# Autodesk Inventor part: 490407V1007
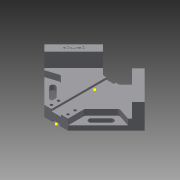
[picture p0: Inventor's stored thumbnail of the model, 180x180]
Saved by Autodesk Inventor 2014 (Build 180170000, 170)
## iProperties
Created: 2019-04
Part Number: 490407V1007
Material: Generic
Document SubType Name: Modeling
Designer: kh
Density: 1 g/cm^3
Appearance: Default
Author: kh
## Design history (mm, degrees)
sketch "Sketch1"
  geometry: L1 (-84.853, 0)-(-35.355, 49.497); L2 (-35.355, 49.497)-(-14.005, 28.147); L3 (-14.005, 28.147)-(14.005, 28.147); L4 (14.005, 28.147)-(35.355, 49.497); L5 (35.355, 49.497)-(84.853, 0); L6 (84.853, 0)-(20, -64.853); L7 (20, -64.853)-(-20, -64.853); L8 (-20, -64.853)-(-84.853, 0); L9 (0, 130.154)-(0, -117.428); L10 (-35.355, 49.497)-(0, 84.853); L11 (35.355, 49.497)-(29.217, 55.636); L12 (29.217, 55.636)-(0, 84.853); L13 (-74.246, -10.607)-(-24.749, 38.891); L14 (24.749, 38.891)-(74.246, -10.607); 1 further point
  constraints: 28 end point, 7 perpendicular, 7 point on line, 4 parallel, 1 vertical
  dimensions: "d6" = 120 distance between parallel lines of L6 L1; "d7" = 120 distance between parallel lines of L8 L5; "d8" = 60 distance from line of point (0, 0) L5; "d9" = 60 distance from line of point (0, 0) L1; "d10" = 40 distance of L6.end L7.end; "d11" = 20 distance from line of L9 L7.end; "d12" = 50 distance from line of L10.end L2; "d13" = 50 distance of L4.end L10.end; "d14" = 93 distance between parallel lines of L7 L3; "d15" = 15 distance between parallel lines of L14 L5; "d16" = 15 distance between parallel lines of L13 L1
extrude "Extrusion1" new body sketch "Sketch1" distance "d17" = 42; taper "d18" = 0 deg
extrude "Extrusion2" join sketch "Sketch1" distance "d19" = 18; taper "d20" = 0 deg
sketch "Sketch2"
  geometry: 1 further point
sketch "Sketch3"
  geometry: L1 (-24.749, 38.891)-(-74.246, -10.607) reference; L2 (-20, -64.853)-(-74.246, -10.607) reference; L3 (20, -64.853)-(-20, -64.853) reference; L4 (74.246, -10.607)-(20, -64.853) reference; L5 (84.853, 0)-(74.246, -10.607) reference; L6 (35.355, 49.497)-(84.853, 0) reference; L7 (24.749, 38.891)-(35.355, 49.497) reference; L8 (74.246, -10.607)-(24.749, 38.891) reference; L9 (-24.749, 38.891)-(-14.005, 28.147) reference; L10 (-35.355, 49.497)-(-24.749, 38.891) reference; L11 (-84.853, 0)-(-35.355, 49.497) reference; L12 (-74.246, -10.607)-(-84.853, 0) reference; L13 (14.005, 28.147)-(24.749, 38.891) reference; L14 (-14.005, 28.147)-(14.005, 28.147) reference; L15 (-70.711, -14.142)-(-49.497, -7.071); L16 (-49.497, -7.071)-(-20, -36.569); L17 (-20, -36.569)-(-20, -64.853); L18 (-49.497, -21.213)-(-32.527, -38.184); L19 (-52.679, -24.395)-(-35.709, -41.366); L20 (-29.345, -35.002)-(-46.315, -18.031); L21 (0, 0)-(0, -64.853); A1 r 4.5 centre (-49.497, -21.213) between (-46.315, -18.031) and (-52.679, -24.395); A2 r 4.5 centre (-32.527, -38.184) between (-35.709, -41.366) and (-29.345, -35.002); 1 further point
  constraints: 16 end point, 4 point on circle, 4 tangent, 3 parallel, 2 centre point, 2 midpoint, 1 perpendicular, 1 point on line
  dimensions: "d21" = 20 distance of L11.start L15.start; "d22" = 20 distance between parallel lines of L16 L2; "d23" = 24 distance of L18.end L18.start; "d24" = 40 distance from line of L11 L18.start; "d25" = 30 distance from line of L11 L15.end; "d26" = 4.5 radius of A2; "d27" = 10 distance from line of L12 point (-41.012, -29.698)
  node "Project Cut Edges1"
extrude "Extrusion3" cut sketch "Sketch3" distance "d28" = 10; taper "d29" = 0 deg
extrude "Extrusion4" cut sketch "Sketch3" stored distance "d30" = 10; taper "d31" = 0 deg
mirror "Mirror1"
sketch "Sketch4"
  geometry: L1 (28, 18)-(12, 18); L2 (12, 18)-(12, 14.5); L3 (12, 14.5)-(28, 14.5); L4 (28, 14.5)-(28, 18); L5 (26, 0)-(14, 0); L6 (14, 0)-(14, 3); L7 (14, 3)-(26, 3); L8 (26, 3)-(26, 0); L9 (0, 0)-(40, 0) reference; L10 (0, 18)-(40, 18) reference; 3 further points
  constraints: 16 end point, 4 midpoint, 4 parallel, 2 horizontal, 2 perpendicular
  dimensions: "d32" = 6 distance from line of L6 point (20, 0); "d33" = 12 distance of L5.start L5.end; "d34" = 3 distance of L7.end L5.start; "d35" = 16 distance of L2.end L3.end; "d37" = 3.5 distance of L3.end L1.start
extrude "Extrusion5" cut sketch "Sketch4" stored distance "d38" = 10; taper "d39" = 0 deg
extrude "Extrusion6" cut sketch "Sketch4" stored distance "d40" = 10; taper "d41" = 0 deg
sketch "Sketch6"
  geometry: L1 (20, -64.853)-(6, -64.853) reference; L2 (6, -64.853)-(6, 28.147) reference; L3 (6, 28.147)-(14.005, 28.147) reference; L4 (14.005, 28.147)-(35.355, 49.497) reference; L5 (35.355, 49.497)-(84.853, 0) reference; L6 (84.853, 0)-(20, -64.853) reference; L7 (-29.345, -35.002)-(-46.315, -18.031) reference; L8 (-52.679, -24.395)-(-35.709, -41.366) reference; L9 (46.315, -18.031)-(29.345, -35.002) reference; L10 (35.709, -41.366)-(52.679, -24.395) reference; L11 (-84.853, 0)-(-35.355, 49.497) reference; L12 (-35.355, 49.497)-(-14.005, 28.147) reference; L13 (-14.005, 28.147)-(-6, 28.147) reference; L14 (-6, 28.147)-(-6, -64.853) reference; L15 (-6, -64.853)-(-20, -64.853) reference; L16 (-20, -64.853)-(-84.853, 0) reference; A1 r 4.5 centre (-32.527, -38.184) between (-35.709, -41.366) and (-29.345, -35.002) reference; A2 r 4.5 centre (-49.497, -21.213) between (-46.315, -18.031) and (-52.679, -24.395) reference; A3 r 4.5 centre (49.497, -21.213) between (52.679, -24.395) and (46.315, -18.031) reference; A4 r 4.5 centre (32.527, -38.184) between (29.345, -35.002) and (35.709, -41.366) reference; 5 further points
  dimensions: "d42" = 14 horizontal distance of point (0, 0) point (-14, -58.853); "d43" = 28 distance of point (14, -58.853) point (-14, -58.853); "d44" = 14 horizontal distance of point (0, 0) point (-14, -46.853); "d45" = 28 distance of point (14, -46.853) point (-14, -46.853); "d46" = 6 distance from line of L1 point (14, -58.853); "d47" = 6 distance from line of L15 point (-14, -58.853); "d48" = 12 distance of point (-14, -58.853) point (-14, -46.853); "d49" = 12 distance of point (14, -58.853) point (14, -46.853)
hole "Hole1" sketch "Sketch6" at (14, -58.853), (14, -46.853), (-14, -46.853), (-14, -58.853) diameter "d50" = 4.5; stored, may be unused: countersink angle "d54" = 90 deg, drill point angle "d56" = 118 deg; dims "d51" = 6, "d52" = 8, "d53" = 10, "d55" = 8
fillet "Fillet1" dims "d57" = 5
fillet "Fillet2" dims "d58" = 5
sketch "Sketch7"
  geometry: L1 (-15.177, 73.236)-(-108.591, -20.178); L2 (-108.591, -20.178)-(-94.425, -34.345); L3 (-94.425, -34.345)-(-1.011, 59.069); L4 (-1.011, 59.069)-(-15.177, 73.236); L5 (-35.355, 49.497)-(-24.749, 38.891) reference; L6 (-24.749, 38.891)-(-74.246, -10.607) reference; L7 (-74.246, -10.607)-(-84.853, 0) reference; L8 (-84.853, 0)-(-35.355, 49.497) reference; L9 (35.355, 49.497)-(84.853, 0) reference; L10 (84.853, 0)-(74.246, -10.607) reference; L11 (74.246, -10.607)-(24.749, 38.891) reference; L12 (24.749, 38.891)-(35.355, 49.497) reference; L13 (-1.011, 59.069)-(-108.591, -20.178); 2 further points
  constraints: 2 end point, 1 midpoint, 2 other
  dimensions: "d59" = 35 distance from line of point (-54.801, 19.445) L5; "d60" = 7.5 distance from line of L8 point (-54.801, 19.445)
emboss "Emboss1" sketch "Sketch7" dims "d6" = 120, "d7" = 120, "d8" = 60, "d9" = 60, "d10" = 40, "d11" = 20, "d12" = 50, "d13" = 50, "d14" = 93, "d15" = 15, "d16" = 15, "d61" = 0.5, "d62" = 0
sketch "Sketch8"
  geometry: 1 further point
body "Solid1"
node "Project Cut Edges2"
node "Project Cut Edges3"
